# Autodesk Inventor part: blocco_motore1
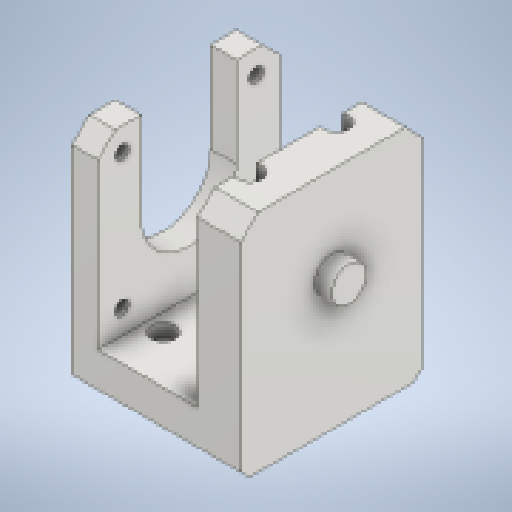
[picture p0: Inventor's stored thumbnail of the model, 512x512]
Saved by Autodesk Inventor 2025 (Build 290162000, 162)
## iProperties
Created: 2025-11
Part Number: blocco_motore1
Material: Plastica ABS
Document SubType Name: Modeling
Designer: R5800u
Density: 1.06 g/cm^3
Appearance: Acciaio
Author: R5800u
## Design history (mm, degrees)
sketch "Schizzo1"
  geometry: L1 (0, 0)-(-15, 0); L2 (-15, 0)-(-15, 52); L3 (-15, 52)-(0, 52); L4 (0, 52)-(0, 0); L5 (-15, 0)-(-47, 0); L6 (-47, 0)-(-47, 10); L7 (-47, 10)-(-15, 10); L8 (-15, 10)-(-15, 0); 1 further point
  constraints: 16 end point, 4 parallel, 2 horizontal, 2 perpendicular
  dimensions: "d0" = 15 distance of L2.end L3.end; "d1" = 52 distance of L1.end L2.end; "d2" = 32 distance of L6.end L7.end; "d3" = 10 distance of L5.end L6.end
extrude "Estrusione1" new body sketch "Schizzo1" stored distance "d4" = 42; taper "d5" = 0 deg
sketch "Schizzo2"
  geometry: L1 (0, 42)-(0, 0) reference; L2 (0, 21)-(32, 21); L3 (32, 42)-(32, 0) reference; C1 r 1.25 at (26.1, 31); C2 r 1.25 at (26.1, 11); C3 r 1.25 at (6.1, 11); C4 r 1.25 at (6.1, 31); 1 further point
  constraints: 4 centre point, 2 end point, 2 midpoint, 1 other
  dimensions: "d31" = 20 distance of C4.centre C3.centre; "d32" = 20 distance of C1.centre C2.centre; "d33" = 20 distance of C2.centre C3.centre; "d34" = 20 distance of C1.centre C4.centre; "d35" = 6.1 distance from line of L1 C3.centre
hole "Foro1" sketch "Schizzo2" at (6.1, 31), (6.1, 11), (26.1, 11), (26.1, 31) diameter "d9" = 2.9; stored, may be unused: countersink angle "d13" = 90 deg, drill point angle "d15" = 118 deg; dims "d10" = 6, "d11" = 5.5, "d12" = 2.9, "d14" = 8
sketch "Schizzo3"
  geometry: C1 r 1.45 at (6.1, 11) reference; C2 r 1.45 at (6.1, 31) reference; C3 r 1.45 at (26.1, 11) reference; C4 r 1.45 at (26.1, 31) reference; 5 further points
  constraints: 4 coincident
hole "Foro2" sketch "Schizzo3" at (6.1, 11), (6.1, 31), (26.1, 11), (26.1, 31) diameter "d16" = 2.9; stored, may be unused: countersink angle "d20" = 90 deg, drill point angle "d22" = 118 deg; dims "d17" = 6, "d18" = 5.5, "d19" = 3.5, "d21" = 8
sketch "Schizzo4"
  geometry: C1 r 1.5 at (10, 15.05) reference; C2 r 1.5 at (17, 8.05) reference; C3 r 1.5 at (17, 22.05) reference; C4 r 1.5 at (24, 15.05) reference; 1 further point
hole "Foro3" sketch "Schizzo4" at (10, 15.05), (17, 8.05), (24, 15.05), (17, 22.05) diameter "d23" = 3.4; stored, may be unused: countersink angle "d27" = 90 deg, drill point angle "d29" = 118 deg; dims "d24" = 6, "d25" = 6.5, "d26" = 3.4, "d28" = 8
sketch "Schizzo5"
  geometry: L1 (0, 0)-(-42, 0) reference; L2 (0, 10)-(0, 0) reference; L3 (-42, 10)-(0, 10) reference; L4 (-42, 0)-(-42, 10) reference; 1 further point
extrude "Estrusione2" join sketch "Schizzo5" distance "d36" = 4; taper "d37" = 0 deg
sketch "Schizzo6"
  geometry: L1 (-36, 0)-(-36, 42) reference; L2 (0, 42)-(0, 0) reference; L3 (0, 0)-(-36, 0) reference; L4 (0, 42)-(-36, 42) reference; L5 (-36, 0)-(-30, 0); L6 (-30, 0)-(-30, 42); L7 (-30, 42)-(-36, 42); L8 (-36, 42)-(-36, 0); L9 (0, 42)-(-36, 42) reference; L10 (0, 0)-(-7, 0); L11 (-7, 0)-(-7, 42); L12 (-7, 42)-(0, 42); L13 (0, 42)-(0, 0); 4 further points
  constraints: 16 end point, 4 parallel, 2 horizontal, 2 perpendicular, 2 point on line
extrude "Estrusione3" join sketch "Schizzo6" distance "d38" = 42; taper "d39" = 0 deg
sketch "Schizzo7"
  geometry: C1 r 1.45 at (24.1, -31) reference; C2 r 2.75 at (24.1, -31); C3 r 2.75 at (24.1, -11); A1 r 2.75 centre (24.1, -31) between (23, -28.48) and (23, -33.52) reference; A2 r 2.75 centre (24.1, -11) between (23, -8.48) and (23, -13.52) reference; A3 r 2.75 centre (24.1, -11) between (23, -13.52) and (23, -8.48) reference; 3 further points
  constraints: 2 centre point, 2 coincident, 1 concentric
extrude "Estrusione4" cut sketch "Schizzo7" distance "d40" = 42; taper "d41" = 0 deg
sketch "Schizzo8"
  geometry: L1 (0, 52)-(-42, 52) reference; L2 (-10, 31.15)-(-32, 31.15); L3 (-32, 31.15)-(-32, 52); L4 (-32, 52)-(-10, 52); L5 (-10, 52)-(-10, 31.15); 4 further points
  constraints: 8 end point, 2 parallel, 1 horizontal, 1 perpendicular, 1 point on line, 2 other
extrude "Estrusione5" cut sketch "Schizzo8" stored distance "d42" = 42; taper "d43" = 0 deg
sketch "Schizzo9"
  geometry: L1 (-32, 31.15)-(-32, 52) reference; L2 (-42, 52)-(-32, 52) reference; L3 (-42, 0)-(-42, 52) reference; L4 (-42, 0)-(0, 0) reference; L5 (0, 0)-(0, 52) reference; L6 (-10, 52)-(0, 52) reference; L7 (-10, 52)-(-10, 31.15) reference; A1 r 11 centre (-21, 31.15) between (-32, 31.15) and (-10, 31.15) reference; 1 further point
extrude "Estrusione6" join sketch "Schizzo9" distance "d44" = 4; taper "d45" = 0 deg
sketch "Schizzo10"
  geometry: L1 (0, 0)-(0, 52) reference; L2 (42, 0)-(0, 0) reference; L3 (42, 0)-(42, 52) reference; L4 (0, 52)-(42, 52) reference; 1 further point
extrude "Estrusione7" join sketch "Schizzo10" distance "d46" = 3; taper "d47" = 0 deg
chamfer "Smusso2" distance "d48" = 2; stored, may be unused: second distance "d49" = 2, angle "d50" = 45 deg
sketch "Schizzo11"
  geometry: C1 r 1.25 at (-5.5, 46.65) reference; C2 r 1.25 at (-36.5, 46.65) reference; C3 r 1.25 at (-36.5, 15.65) reference; C4 r 1.25 at (-5.5, 15.65) reference; 1 further point
hole "Foro4" sketch "Schizzo11" at (-5.5, 15.65), (-5.5, 46.65), (-36.5, 46.65), (-36.5, 15.65) diameter "d51" = 3.2; stored, may be unused: countersink angle "d55" = 90 deg, drill point angle "d57" = 118 deg; dims "d52" = 6, "d53" = 6, "d54" = 1.5, "d56" = 12
chamfer "Smusso3" distance "d58" = 4; stored, may be unused: second distance "d59" = 2, angle "d60" = 45 deg
sketch "Schizzo12"
  geometry: C1 r 4 at (21, 31.15); A1 r 11 centre (21, 31.15) between (10, 31.15) and (32, 31.15) reference; 1 further point
  constraints: 1 centre point, 1 coincident
  dimensions: "d61" = 8 diameter of C1
extrude "Estrusione8" join sketch "Schizzo12" distance "d62" = 6; taper "d63" = 0 deg
sketch "Schizzo13"
  geometry: C1 r 4 at (21, 31.15) reference; C2 r 5.5 at (21, 31.15); 1 further point
  constraints: 1 centre point, 1 coincident
  dimensions: "d64" = 11 diameter of C2
extrude "Estrusione9" join sketch "Schizzo13" distance "d65" = 1; taper "d66" = 0 deg
node "Solido1"
node "Riferimento5"
node "Riferimento6"
node "Riferimento7"
node "Riferimento8"
node "Linea chiusa proiettata1"
node "Riferimento10"
node "Linea chiusa proiettata2"
node "Linea chiusa proiettata3"
node "Riferimento11"
node "Riferimento12"
node "Riferimento13"
node "Riferimento14"
